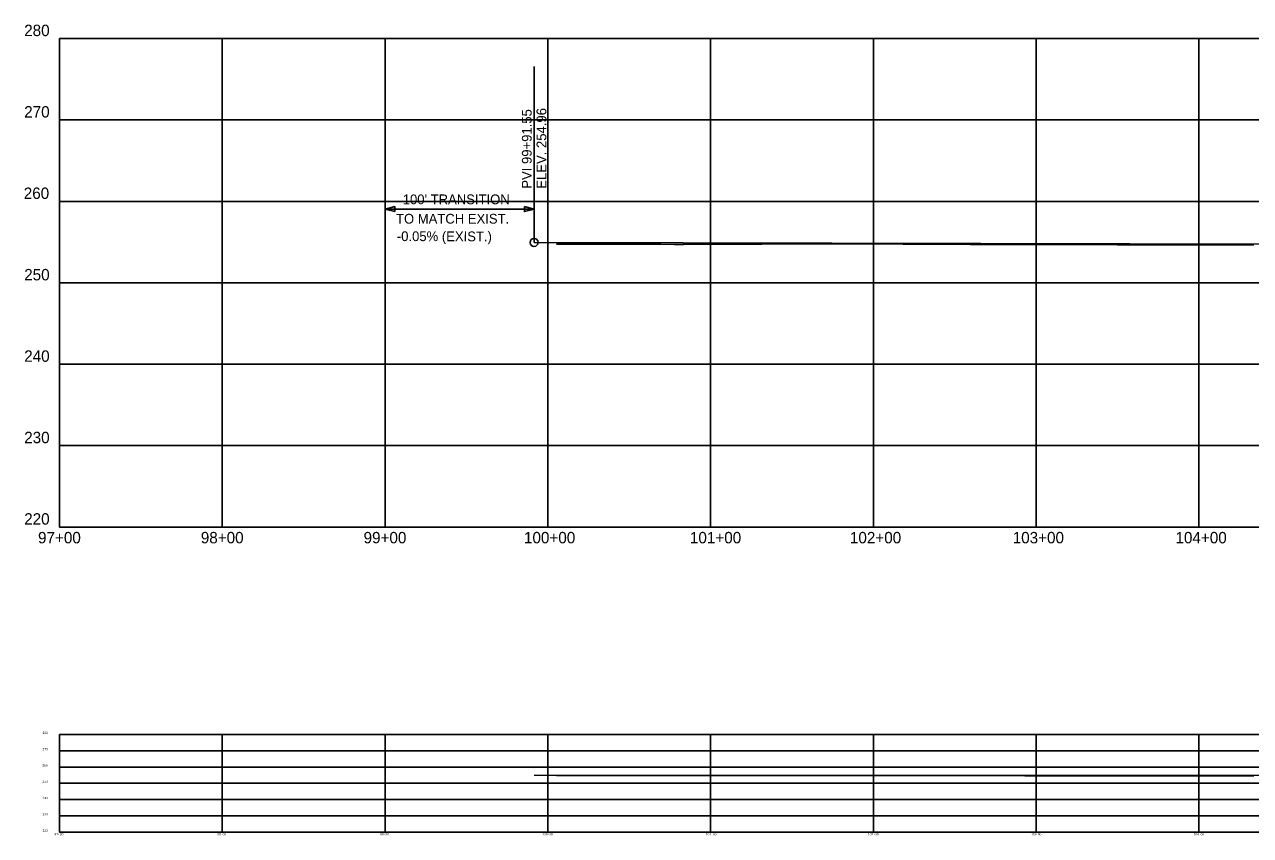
# Model space of a CAD drawing. Extents: x 1932071 to 1934815, y 598385 to 598883.
# Drawn here: x 1932071 to 1932824, y 598385 to 598883 of the extents above; entities that cross this region are included whole.
import ezdxf

# ---------------------------------------------------------------- set-up
doc = ezdxf.new("R2010")
doc.units = 0
for name, color, linetype in [('R_Annotation', 7, 'Continuous'), ('R_Axis', 7, 'Continuous'), ('R_Axis Annot', 7, 'Continuous'), ('R_Exist Surface', 7, 'Continuous'), ('R_Grid', 7, 'Continuous'), ('R_Vert Alg', 7, 'Continuous'), ('R_Vert Alg Annot', 7, 'Continuous')]:
    doc.layers.add(name, color=color, linetype=linetype)

msp = doc.modelspace()

# ---------------------------------------------------------------- linework, layer by layer
at = {"layer": 'R_Annotation'}
for p, q in [((1932292.67, 598749.34), (1932292.67, 598772.81)), ((1932384.22, 598769.81), (1932292.67, 598769.81)), ((1932384.22, 598749.34), (1932384.22, 598772.81))]:
    msp.add_line(p, q, dxfattribs=at)
for points in [[(1932298.67, 598768.31), (1932292.67, 598769.81), (1932298.67, 598771.31)], [(1932378.22, 598771.31), (1932384.22, 598769.81), (1932378.22, 598768.31)]]:
    msp.add_lwpolyline(points, close=True, dxfattribs=at)
at = {"layer": 'R_Axis'}
for p, q in [((1932092.67, 598574.55), (1932092.67, 598874.55)), ((1932092.67, 598574.55), (1934792.67, 598574.55)), ((1932092.67, 598387.17), (1932092.67, 598447.17)), ((1932092.67, 598387.17), (1934792.67, 598387.17))]:
    msp.add_line(p, q, dxfattribs=at)
at = {"layer": 'R_Exist Surface'}
for points in [[(1932397.97, 598748.2), (1932405.75, 598748.22), (1932409.8, 598748.23), (1932411.52, 598748.23), (1932423.31, 598748.26), (1932424.2, 598748.26), (1932427.29, 598748.25), (1932435.84, 598748.24), (1932436.8, 598748.24), (1932448.36, 598748.22), (1932448.82, 598748.22), (1932449.41, 598748.21), (1932460.89, 598748.19), (1932462.03, 598748.19), (1932470.36, 598748.17), (1932473.41, 598748.17), (1932475.9, 598748.17), (1932491.89, 598748.24), (1932497.78, 598748.26), (1932500.67, 598748.27), (1932513.42, 598748.31), (1932522.17, 598748.34), (1932523.93, 598748.35), (1932534.92, 598748.38), (1932534.96, 598748.38), (1932536.81, 598748.38), (1932547.68, 598748.41), (1932549.72, 598748.42), (1932556.49, 598748.43), (1932560.44, 598748.44), (1932562.64, 598748.45), (1932573.2, 598748.47), (1932578.02, 598748.46), (1932590.25, 598748.41), (1932594.35, 598748.4), (1932599.56, 598748.38), (1932610.98, 598748.34), (1932615.5, 598748.32), (1932621.09, 598748.3), (1932631.63, 598748.26), (1932636.66, 598748.24), (1932642.62, 598748.22), (1932652.2, 598748.17), (1932657.81, 598748.15), (1932664.16, 598748.14), (1932664.94, 598748.14), (1932682.57, 598748.1), (1932685.69, 598748.09), (1932691.39, 598748.08), (1932707.23, 598748.03), (1932707.28, 598748.03), (1932717.43, 598748.02), (1932728.76, 598747.98), (1932730.6, 598747.97), (1932742.67, 598747.93), (1932750.29, 598747.92), (1932753.96, 598747.91), (1932760.38, 598747.88), (1932767.58, 598747.88), (1932771.83, 598747.86), (1932773.44, 598747.85), (1932781.19, 598747.85), (1932789.6, 598747.84), (1932793.36, 598747.82), (1932794.79, 598747.82), (1932803.84, 598747.81), (1932808.38, 598747.79), (1932814.89, 598747.79), (1932826.42, 598747.78)], [(1932397.97, 598421.9), (1932405.75, 598421.9), (1932409.8, 598421.9), (1932411.52, 598421.9), (1932423.31, 598421.91), (1932424.2, 598421.91), (1932427.29, 598421.91), (1932435.84, 598421.9), (1932436.8, 598421.9), (1932448.36, 598421.9), (1932448.82, 598421.9), (1932449.41, 598421.9), (1932460.89, 598421.89), (1932462.03, 598421.89), (1932470.36, 598421.89), (1932473.41, 598421.89), (1932475.9, 598421.89), (1932491.89, 598421.9), (1932497.78, 598421.91), (1932500.67, 598421.91), (1932513.42, 598421.92), (1932522.17, 598421.93), (1932523.93, 598421.93), (1932534.92, 598421.93), (1932534.96, 598421.93), (1932536.81, 598421.93), (1932547.68, 598421.94), (1932549.72, 598421.94), (1932556.49, 598421.94), (1932560.44, 598421.94), (1932562.64, 598421.95), (1932573.2, 598421.95), (1932578.02, 598421.95), (1932590.25, 598421.94), (1932594.35, 598421.94), (1932599.56, 598421.93), (1932610.98, 598421.92), (1932615.5, 598421.92), (1932621.09, 598421.92), (1932631.63, 598421.91), (1932636.66, 598421.9), (1932642.62, 598421.9), (1932652.2, 598421.89), (1932657.81, 598421.89), (1932664.16, 598421.88), (1932664.94, 598421.88), (1932682.57, 598421.88), (1932685.69, 598421.87), (1932691.39, 598421.87), (1932707.23, 598421.86), (1932707.28, 598421.86), (1932717.43, 598421.86), (1932728.76, 598421.85), (1932730.6, 598421.85), (1932742.67, 598421.84), (1932750.29, 598421.84), (1932753.96, 598421.84), (1932760.38, 598421.83), (1932767.58, 598421.83), (1932771.83, 598421.83), (1932773.44, 598421.83), (1932781.19, 598421.83), (1932789.6, 598421.82), (1932793.36, 598421.82), (1932794.79, 598421.82), (1932803.84, 598421.82), (1932808.38, 598421.81), (1932814.89, 598421.81), (1932826.42, 598421.81)]]:
    msp.add_lwpolyline(points, dxfattribs=at)
at = {"layer": 'R_Grid'}
for p, q in [((1932092.67, 598874.55), (1934792.67, 598874.55)), ((1932092.67, 598874.55), (1934792.67, 598874.55)), ((1932192.67, 598574.55), (1932192.67, 598874.55)), ((1932292.67, 598574.55), (1932292.67, 598874.55)), ((1932392.67, 598574.55), (1932392.67, 598874.55)), ((1932492.67, 598574.55), (1932492.67, 598874.55)), ((1932592.67, 598574.55), (1932592.67, 598874.55)), ((1932692.67, 598574.55), (1932692.67, 598874.55)), ((1932792.67, 598574.55), (1932792.67, 598874.55)), ((1932092.67, 598824.55), (1934792.67, 598824.55)), ((1932092.67, 598774.55), (1934792.67, 598774.55)), ((1932092.67, 598724.55), (1934792.67, 598724.55)), ((1932092.67, 598674.55), (1934792.67, 598674.55)), ((1932092.67, 598624.55), (1934792.67, 598624.55)), ((1932092.67, 598447.17), (1934792.67, 598447.17)), ((1932092.67, 598447.17), (1934792.67, 598447.17)), ((1932192.67, 598387.17), (1932192.67, 598447.17)), ((1932292.67, 598387.17), (1932292.67, 598447.17)), ((1932392.67, 598387.17), (1932392.67, 598447.17)), ((1932492.67, 598387.17), (1932492.67, 598447.17)), ((1932592.67, 598387.17), (1932592.67, 598447.17)), ((1932692.67, 598387.17), (1932692.67, 598447.17)), ((1932792.67, 598387.17), (1932792.67, 598447.17)), ((1932092.67, 598437.17), (1934792.67, 598437.17)), ((1932092.67, 598427.17), (1934792.67, 598427.17)), ((1932092.67, 598417.17), (1934792.67, 598417.17)), ((1932092.67, 598407.17), (1934792.67, 598407.17)), ((1932092.67, 598397.17), (1934792.67, 598397.17))]:
    msp.add_line(p, q, dxfattribs=at)
at = {"layer": 'R_Vert Alg'}
for p, q in [((1932384.22, 598749.34), (1932956.67, 598747.91)), ((1932384.22, 598422.12), (1932956.67, 598421.84))]:
    msp.add_line(p, q, dxfattribs=at)
at = {"layer": 'R_Vert Alg Annot'}
for p, q in [((1932384.22, 598779.34), (1932384.22, 598857.34)), ((1932384.22, 598749.34), (1932384.22, 598779.34))]:
    msp.add_line(p, q, dxfattribs=at)
msp.add_circle((1932384.22, 598749.34), 2.5, dxfattribs=at)

# ---------------------------------------------------------------- texts
at = {"layer": 'R_Annotation'}
for s, p in [("100' TRANSITION", (1932303.51, 598772.79)), ('TO MATCH EXIST.', (1932299.37, 598760.89))]:
    msp.add_text(s, height=6, rotation=0.00482, dxfattribs=at).set_placement(p)
at = {"layer": 'R_Axis Annot'}
for s, height, p in [('280', 7, (1932070.97, 598876.05)), ('280', 7, (1932070.97, 598876.05)), ('270', 7, (1932070.97, 598826.05)), ('260', 7, (1932070.69, 598776.05)), ('250', 7, (1932070.97, 598726.05)), ('240', 7, (1932070.97, 598676.05)), ('230', 7, (1932070.97, 598626.05)), ('220', 7, (1932070.97, 598576.05)), ('97+00', 7, (1932079.46, 598564.55)), ('-', 0.0001, (1932092.67, 598574.55)), ('98+00', 7, (1932179.46, 598564.55)), ('99+00', 7, (1932279.46, 598564.55)), ('100+00', 7, (1932378, 598564.55)), ('101+00', 7, (1932479.94, 598564.55)), ('102+00', 7, (1932578.23, 598564.55)), ('103+00', 7, (1932678.23, 598564.55)), ('104+00', 7, (1932778.23, 598564.55)), ('280', 1.4, (1932082.24, 598447.47)), ('280', 1.4, (1932082.24, 598447.47)), ('270', 1.4, (1932082.24, 598437.47)), ('260', 1.4, (1932082.17, 598427.47)), ('250', 1.4, (1932082.24, 598417.47)), ('240', 1.4, (1932082.24, 598407.47)), ('230', 1.4, (1932082.24, 598397.47)), ('220', 1.4, (1932082.24, 598387.47)), ('97+00', 1.4, (1932089.59, 598385.17)), ('-', 1.4, (1932092.33, 598386.47)), ('98+00', 1.4, (1932189.59, 598385.17)), ('99+00', 1.4, (1932289.59, 598385.17)), ('100+00', 1.4, (1932389.24, 598385.17)), ('101+00', 1.4, (1932489.7, 598385.17)), ('102+00', 1.4, (1932589.3, 598385.17)), ('103+00', 1.4, (1932689.3, 598385.17)), ('104+00', 1.4, (1932789.3, 598385.17))]:
    msp.add_text(s, height=height, dxfattribs=at).set_placement(p)
at = {"layer": 'R_Vert Alg Annot'}
for s, rotation, p in [('PVI 99+91.55', 90, (1932382.72, 598782.34)), ('ELEV. 254.96', 90, (1932391.72, 598782.34)), ('-0.05% (EXIST.)', 359.84683, (1932299.88, 598750.17))]:
    msp.add_text(s, height=6, rotation=rotation, dxfattribs=at).set_placement(p)

doc.saveas('drawing.dxf')
